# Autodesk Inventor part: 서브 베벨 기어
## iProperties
Created: 2014-10
Part Number: 서브 베벨 기어
Material: Steel, Mild
Document SubType Name: Modeling
Designer: KYOUNG IL JANG
Categories: <?xml version="1.0" encoding="UTF-16"?> <MemberInstance><Categories><FamilyTemplate><FamilyTemplateParameter ValueType="xs:double" Id="1" ObjectReferenceKey="da
Mass: 134.866 g
Surface Area: 63.6518 cm^2
Volume: 17.1585 cm^3
Density: 7.86 g/cm^3
CustomPartVersion: 1
Company: 한국ATC센터
Author: KYOUNG IL JANG
Revision Number: 1
